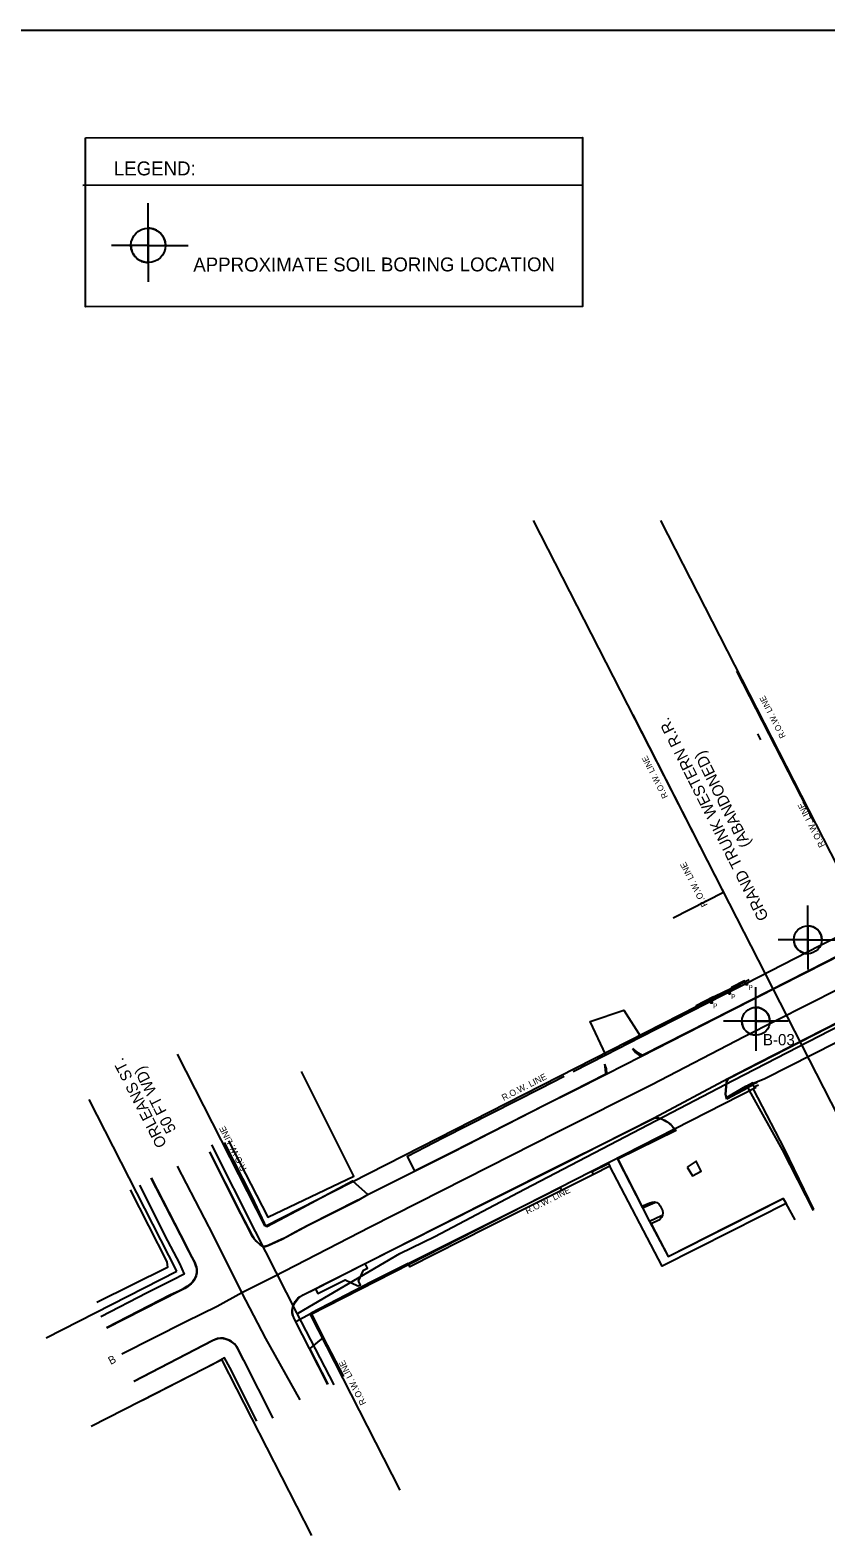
# Model space of a CAD drawing. Extents: x 19007.1 to 19038.2, y 21497.8 to 21516.9.
# Drawn here: x 19024.02 to 19030.01, y 21505.53 to 21516.88 of the extents above; entities that cross this region are included whole.
import ezdxf

# ---------------------------------------------------------------- set-up
doc = ezdxf.new("R2010")
doc.units = 0
for name, color, linetype in [('BORDER', 7, 'Continuous'), ('DETAIL_TEXT_DIMEN_PR', 7, 'Continuous'), ('G-ANNO-TTLB', 7, 'Continuous'), ('TYPICAL_TEXT_DIMEN_PR', 7, 'Continuous'), ('V-ANNO-TEXT', 7, 'Continuous'), ('V-BLDG-OTLN', 7, 'Continuous'), ('V-DEMO-PVMT', 7, 'Continuous'), ('V-PROP-RWAY', 7, 'Continuous'), ('V-PROP-RWAY-IDEN', 7, 'Continuous'), ('V-PVMT-CNTR', 7, 'Continuous'), ('V-PVMT-ROAD', 7, 'Continuous'), ('V-SITE-FEAT-DEMO', 7, 'Continuous'), ('V-SITE-FENC', 7, 'Continuous'), ('V-SITE-STRS', 7, 'Continuous'), ('V-SITE-WALK', 7, 'Continuous'), ('V-UTIL-OVHD', 7, 'Continuous')]:
    doc.layers.add(name, color=color, linetype=linetype)

msp = doc.modelspace()

# ---------------------------------------------------------------- linework, layer by layer
at = {"layer": 'G-ANNO-TTLB'}
msp.add_lwpolyline([(19036.423, 21497.766), (19007.08, 21497.766), (19007.08, 21516.881), (19036.423, 21516.881)], close=True, dxfattribs=at)
at = {"layer": 'TYPICAL_TEXT_DIMEN_PR'}
for p, q in [((19024.417, 21515.713), (19028.178, 21515.715)), ((19024.91, 21515.26), (19024.91, 21515.579)), ((19024.91, 21515.26), (19024.634, 21515.26)), ((19024.91, 21515.26), (19024.91, 21514.985)), ((19024.91, 21515.26), (19025.211, 21515.26)), ((19029.874, 21510.031), (19029.874, 21510.289)), ((19029.874, 21510.031), (19029.651, 21510.03)), ((19029.874, 21510.031), (19029.874, 21509.807)), ((19029.874, 21510.031), (19030.118, 21510.031)), ((19029.483, 21509.417), (19029.483, 21509.675)), ((19029.484, 21509.417), (19029.24, 21509.417)), ((19029.483, 21509.417), (19029.483, 21509.194)), ((19029.727, 21509.417), (19029.483, 21509.417))]:
    msp.add_line(p, q, dxfattribs=at)
msp.add_lwpolyline([(19024.437, 21516.071), (19028.178, 21516.073), (19028.179, 21514.8), (19024.438, 21514.797)], close=True, dxfattribs=at)
for points in [[(19024.91, 21515.39), (19024.91, 21515.26), (19025.04, 21515.26)], [(19024.91, 21515.13), (19024.91, 21515.26), (19024.78, 21515.26)], [(19029.874, 21510.136), (19029.874, 21510.031), (19029.979, 21510.031)], [(19029.874, 21509.925), (19029.874, 21510.031), (19029.769, 21510.031)], [(19029.483, 21509.522), (19029.483, 21509.417), (19029.588, 21509.417)], [(19029.483, 21509.312), (19029.483, 21509.417), (19029.378, 21509.417)]]:
    msp.add_lwpolyline(points, dxfattribs=at)
for centre, radius in [((19024.91, 21515.26), 0.13), ((19029.874, 21510.031), 0.105), ((19029.483, 21509.417), 0.105)]:
    msp.add_circle(centre, radius, dxfattribs=at)
for centre, radius, start, end in [((19024.91, 21515.26), 0.13, 0.0399, 90.0399), ((19024.91, 21515.26), 0.13, 180.0399, 270.0399), ((19029.874, 21510.031), 0.105, 0.0399, 90.0399), ((19029.874, 21510.031), 0.105, 180.0399, 270.0399), ((19029.483, 21509.417), 0.105, 0.0399, 90.0399), ((19029.483, 21509.417), 0.105, 180.0399, 270.0399)]:
    msp.add_arc(centre, radius, start, end, dxfattribs=at)
at = {"layer": 'V-BLDG-OTLN'}
for points in [[(19029.305, 21509.654), (19029.299, 21509.665), (19029.168, 21509.601), (19029.176, 21509.588)], [(19029.408, 21509.702), (19029.398, 21509.722), (19029.3, 21509.671), (19029.308, 21509.654)], [(19029.172, 21509.587), (19029.165, 21509.601), (19029.034, 21509.534), (19029.041, 21509.52)], [(19029.494, 21508.956), (19029.465, 21508.943), (19029.459, 21508.953), (19029.409, 21508.926), (19029.415, 21508.915), (19029.459, 21508.938), (19029.468, 21508.923), (19029.502, 21508.939)], [(19029.78, 21507.921), (19029.71, 21508.045), (19029.294, 21507.835), (19028.777, 21507.573), (19028.385, 21508.325), (19028.26, 21508.263), (19028.02, 21508.142), (19027.462, 21507.863), (19026.879, 21507.569), (19026.866, 21507.593), (19026.589, 21507.455), (19026.137, 21507.219), (19026.227, 21507.037), (19026.379, 21506.741)], [(19028.26, 21508.263), (19028.251, 21508.285), (19028.374, 21508.346), (19028.385, 21508.325)], [(19026.866, 21507.593), (19027.449, 21507.884), (19028.011, 21508.165), (19028.02, 21508.142)], [(19025.728, 21506.405), (19025.524, 21506.81), (19025.483, 21506.883), (19025.413, 21506.843), (19024.867, 21506.562)]]:
    msp.add_lwpolyline(points, dxfattribs=at)
at = {"layer": 'V-DEMO-PVMT'}
for points in [[(19028.097, 21508.889), (19028.362, 21509.022), (19028.49, 21509.087), (19028.616, 21509.152), (19029.3, 21509.501), (19030.016, 21509.866), (19030.652, 21510.19), (19030.704, 21510.219), (19030.996, 21510.373)], [(19028.108, 21509.039), (19028.353, 21509.164), (19028.617, 21509.301), (19029.241, 21509.619), (19029.408, 21509.702), (19029.965, 21509.988), (19030.523, 21510.268), (19030.468, 21510.372)], [(19028.555, 21509.213), (19028.585, 21509.187), (19028.628, 21509.161), (19029.299, 21509.504), (19030.015, 21509.868), (19030.59, 21510.166), (19030.626, 21510.182)], [(19028.305, 21508.482), (19028.718, 21508.689), (19029.272, 21508.987), (19029.505, 21509.106), (19030.229, 21509.475), (19030.738, 21509.734), (19030.887, 21509.807), (19031.202, 21509.968)], [(19029.262, 21508.846), (19029.258, 21508.867), (19029.265, 21508.958), (19029.277, 21508.987), (19029.507, 21509.104), (19030.228, 21509.473), (19030.74, 21509.732), (19030.888, 21509.804)], [(19028.554, 21509.212), (19028.578, 21509.182), (19028.616, 21509.152)], [(19028.097, 21508.891), (19028.354, 21509.021), (19028.351, 21509.057), (19028.347, 21509.093)], [(19028.362, 21509.022), (19028.358, 21509.058), (19028.347, 21509.093)], [(19029.265, 21508.831), (19029.255, 21508.868), (19029.262, 21508.957), (19029.272, 21508.987)], [(19028.306, 21508.481), (19028.718, 21508.687), (19028.724, 21508.689), (19028.738, 21508.691), (19028.751, 21508.689), (19028.778, 21508.679), (19028.812, 21508.66), (19028.828, 21508.649), (19028.852, 21508.627), (19028.863, 21508.615), (19028.869, 21508.608)], [(19028.718, 21508.689), (19028.746, 21508.688), (19028.759, 21508.686), (19028.778, 21508.681), (19028.796, 21508.673), (19028.808, 21508.666), (19028.83, 21508.651), (19028.842, 21508.64), (19028.865, 21508.616), (19028.882, 21508.594)], [(19028.869, 21508.608), (19028.879, 21508.594)]]:
    msp.add_lwpolyline(points, dxfattribs=at)
at = {"layer": 'V-PROP-RWAY'}
for p, q in [((19031.47, 21506.028), (19027.81, 21513.188)), ((19028.765, 21513.188), (19032.424, 21506.028)), ((19029.337, 21512.053), (19029.92, 21510.918)), ((19028.557, 21511.724), (19029.24, 21510.388)), ((19029.496, 21511.581), (19029.518, 21511.537)), ((19029.24, 21510.388), (19028.861, 21510.194)), ((19025.791, 21507.875), (19029.433, 21509.733)), ((19025.791, 21507.875), (19025.131, 21509.169)), ((19028.871, 21508.608), (19029.486, 21508.922)), ((19025.126, 21507.536), (19024.466, 21508.829)), ((19026.13, 21507.21), (19028.871, 21508.608)), ((19024.141, 21507.033), (19025.126, 21507.536)), ((19026.806, 21505.886), (19026.13, 21507.21)), ((19024.48, 21506.368), (19025.465, 21506.871)), ((19026.141, 21505.546), (19025.465, 21506.871))]:
    msp.add_line(p, q, dxfattribs=at)
at = {"layer": 'V-PVMT-CNTR'}
for points in [[(19024.711, 21506.912), (19025.192, 21507.157), (19025.429, 21507.272), (19025.614, 21507.374), (19025.854, 21507.494), (19026.581, 21507.868), (19027.297, 21508.234), (19027.984, 21508.583), (19028.701, 21508.941), (19029.396, 21509.302), (19030.11, 21509.663), (19030.749, 21509.989), (19031.403, 21510.322), (19032.101, 21510.681), (19032.774, 21511.026), (19033.516, 21511.404), (19034.256, 21511.778), (19034.944, 21512.128), (19035.373, 21512.345)], [(19026.053, 21506.566), (19025.794, 21507.028), (19025.615, 21507.374), (19025.401, 21507.805), (19025.131, 21508.327)]]:
    msp.add_lwpolyline(points, dxfattribs=at)
at = {"layer": 'V-PVMT-ROAD'}
for points in [[(19028.353, 21509.164), (19028.235, 21509.416), (19028.49, 21509.501), (19028.617, 21509.301)], [(19025.37, 21508.432), (19025.605, 21507.966), (19025.686, 21507.807), (19025.697, 21507.791), (19025.722, 21507.762), (19025.75, 21507.736), (19025.769, 21507.724), (19025.779, 21507.721), (19025.79, 21507.721), (19025.812, 21507.729), (19025.918, 21507.777), (19026.114, 21507.881), (19026.495, 21508.072), (19026.562, 21508.112), (19027.194, 21508.429), (19027.906, 21508.793), (19028.097, 21508.889)], [(19026.915, 21508.292), (19027.19, 21508.43), (19027.904, 21508.793), (19028.097, 21508.891)], [(19029.263, 21508.844), (19029.276, 21508.848), (19029.409, 21508.926)], [(19029.917, 21507.992), (19029.683, 21508.449), (19029.448, 21508.874), (19029.425, 21508.916), (19029.265, 21508.831)], [(19028.879, 21508.594), (19028.441, 21508.379), (19028.631, 21508.012), (19028.683, 21507.91), (19028.823, 21507.645), (19029.273, 21507.872), (19029.689, 21508.082), (19029.71, 21508.045)], [(19028.882, 21508.594), (19028.443, 21508.379), (19028.626, 21508.024), (19028.685, 21508.049), (19028.702, 21508.056), (19028.72, 21508.057), (19028.737, 21508.052), (19028.752, 21508.042), (19028.762, 21508.028), (19028.763, 21508.027), (19028.781, 21507.993), (19028.784, 21507.974), (19028.781, 21507.956), (19028.773, 21507.939), (19028.759, 21507.925), (19028.752, 21507.92), (19028.696, 21507.891), (19028.824, 21507.646), (19029.273, 21507.874), (19029.69, 21508.085)], [(19025.371, 21508.434), (19025.607, 21507.967), (19025.689, 21507.809), (19025.701, 21507.789), (19025.708, 21507.78), (19025.723, 21507.763), (19025.742, 21507.744), (19025.752, 21507.736), (19025.769, 21507.726), (19025.778, 21507.724), (19025.789, 21507.723), (19025.796, 21507.725), (19025.812, 21507.731), (19025.916, 21507.778), (19025.935, 21507.787), (19026.021, 21507.833), (19026.11, 21507.881), (19026.493, 21508.074)], [(19026.262, 21506.683), (19026.124, 21506.954), (19026.019, 21507.158), (19026.005, 21507.186), (19025.995, 21507.209), (19025.993, 21507.221), (19025.993, 21507.241), (19025.995, 21507.255), (19026.003, 21507.282), (19026.016, 21507.306), (19026.023, 21507.317), (19026.037, 21507.331), (19026.049, 21507.341), (19026.076, 21507.356), (19026.562, 21507.603), (19027.438, 21508.047), (19028.094, 21508.376), (19028.305, 21508.482)], [(19026.02, 21507.157), (19026.006, 21507.186), (19026.001, 21507.198), (19025.996, 21507.222), (19025.996, 21507.242), (19025.998, 21507.256), (19026.006, 21507.282), (19026.015, 21507.299), (19026.022, 21507.31), (19026.039, 21507.329), (19026.062, 21507.348), (19026.076, 21507.356), (19026.168, 21507.402), (19026.543, 21507.592), (19027.439, 21508.045), (19028.095, 21508.375), (19028.306, 21508.481)], [(19028.965, 21508.318), (19029.007, 21508.254), (19029.072, 21508.289), (19029.033, 21508.364), (19028.965, 21508.318)], [(19024.93, 21508.235), (19025.151, 21507.809), (19025.212, 21507.685), (19025.237, 21507.639), (19025.257, 21507.598), (19025.266, 21507.576), (19025.27, 21507.564), (19025.273, 21507.548), (19025.273, 21507.523), (19025.268, 21507.499), (19025.264, 21507.489), (19025.253, 21507.469), (19025.243, 21507.455), (19025.23, 21507.442), (19025.201, 21507.42), (19025.164, 21507.397), (19025.144, 21507.387), (19025.078, 21507.356), (19024.596, 21507.108)], [(19024.933, 21508.237), (19025.152, 21507.809), (19025.239, 21507.641), (19025.26, 21507.6), (19025.269, 21507.577), (19025.273, 21507.566), (19025.275, 21507.549), (19025.275, 21507.524), (19025.27, 21507.499), (19025.263, 21507.483), (19025.252, 21507.462), (19025.245, 21507.453), (19025.233, 21507.44), (19025.224, 21507.432), (19025.205, 21507.418), (19025.185, 21507.406), (19025.144, 21507.386), (19024.598, 21507.106)], [(19024.775, 21508.149), (19025.049, 21507.605), (19025.055, 21507.564), (19024.522, 21507.3)], [(19026.171, 21507.394), (19026.186, 21507.367), (19026.391, 21507.469), (19026.488, 21507.425), (19026.507, 21507.433), (19026.493, 21507.461), (19026.53, 21507.544), (19026.56, 21507.559), (19026.543, 21507.592)], [(19026.02, 21507.157), (19026.137, 21507.219)], [(19026.227, 21507.037), (19026.125, 21506.954)], [(19025.849, 21506.429), (19025.63, 21506.866), (19025.583, 21506.954), (19025.576, 21506.966), (19025.558, 21506.988), (19025.533, 21507.008), (19025.519, 21507.016), (19025.49, 21507.027), (19025.475, 21507.031), (19025.453, 21507.032), (19025.432, 21507.029), (19025.419, 21507.024), (19025.392, 21507.012), (19024.802, 21506.705)], [(19025.628, 21506.865), (19025.581, 21506.955), (19025.574, 21506.967), (19025.557, 21506.987), (19025.545, 21506.997), (19025.519, 21507.013), (19025.49, 21507.024), (19025.475, 21507.027), (19025.453, 21507.029), (19025.433, 21507.026), (19025.419, 21507.022), (19025.393, 21507.011), (19024.803, 21506.704)], [(19026.264, 21506.684), (19026.125, 21506.954)]]:
    msp.add_lwpolyline(points, dxfattribs=at)
at = {"layer": 'V-SITE-FEAT-DEMO'}
for centre, radius in [((19029.414, 21509.697), 0.00597), ((19029.414, 21509.697), 0.00299), ((19029.149, 21509.559), 0.00597), ((19029.149, 21509.559), 0.00299), ((19029.285, 21509.628), 0.00597), ((19029.285, 21509.628), 0.00299)]:
    msp.add_circle(centre, radius, dxfattribs=at)
at = {"layer": 'V-SITE-FENC'}
for points in [[(19025.515, 21508.516), (19025.811, 21507.943), (19026.456, 21508.251), (19026.064, 21509.039)], [(19029.919, 21508), (19029.699, 21508.457), (19029.464, 21508.907)]]:
    msp.add_lwpolyline(points, dxfattribs=at)
at = {"layer": 'V-SITE-STRS'}
for points in [[(19028.631, 21508.012), (19028.723, 21508.052)], [(19028.773, 21507.952), (19028.683, 21507.91)]]:
    msp.add_lwpolyline(points, dxfattribs=at)
at = {"layer": 'V-SITE-WALK'}
for points in [[(19029.263, 21508.844), (19029.408, 21508.928), (19029.551, 21508.987), (19030.268, 21509.35), (19030.603, 21509.523), (19030.614, 21509.505)], [(19026.915, 21508.293), (19026.861, 21508.401), (19027.132, 21508.541), (19027.859, 21508.911), (19028.039, 21509.003)], [(19025.481, 21508.505), (19025.69, 21508.096), (19025.783, 21507.896), (19025.803, 21507.871), (19025.94, 21507.944), (19026.073, 21508.014), (19026.268, 21508.12), (19026.447, 21508.216), (19026.562, 21508.112)], [(19024.843, 21508.183), (19025.056, 21507.764), (19025.144, 21507.592), (19025.181, 21507.513), (19025.093, 21507.468), (19024.903, 21507.373), (19024.553, 21507.191)]]:
    msp.add_lwpolyline(points, dxfattribs=at)
at = {"layer": 'V-UTIL-OVHD'}
for points in [[(19026.038, 21507.219), (19026.804, 21507.669), (19027.068, 21507.797), (19027.741, 21508.152), (19029.314, 21508.974), (19031.251, 21509.972), (19031.886, 21510.285), (19032.984, 21510.845)], [(19025.385, 21508.487), (19025.714, 21507.833), (19026.025, 21507.222), (19026.307, 21506.68)]]:
    msp.add_lwpolyline(points, dxfattribs=at)

# ---------------------------------------------------------------- texts
msp.add_text('B', height=0.0597, rotation=27.0313).set_placement((19024.627, 21506.829))
at = {"layer": 'BORDER'}
for s, height, p in [('LEGEND:', 0.105, (19024.651, 21515.787)), ('APPROXIMATE SOIL BORING LOCATION', 0.10498, (19025.249, 21515.063))]:
    msp.add_text(s, height=height, rotation=0.0399, dxfattribs=at).set_placement(p)
at = {"layer": 'DETAIL_TEXT_DIMEN_PR'}
msp.add_text('B-03', height=0.085, rotation=0.0399, dxfattribs=at).set_placement((19029.536, 21509.236))
at = {"layer": 'V-ANNO-TEXT'}
for s, height, rotation, p in [('GRAND TRUNK WESTERN R.R.', 0.08503, 116.6596, (19029.582, 21510.2)), ('(ABANDONED)', 0.08503, 116.6596, (19029.448, 21510.751)), ('ORLEANS ST. ', 0.08361, 117.0313, (19025.052, 21508.491)), ('50 FT WD)', 0.0836, 117.0313, (19025.122, 21508.6))]:
    msp.add_text(s, height=height, rotation=rotation, dxfattribs=at).set_placement(p)
at = {"layer": 'V-PROP-RWAY-IDEN'}
for height, rotation, p in [(0.04535, 117.1686, (19029.709, 21511.562)), (0.04535, 117.1686, (19028.823, 21511.109)), (0.04778, 117.0313, (19030.005, 21510.741)), (0.04778, 117.0313, (19029.121, 21510.293)), (0.04778, 27.0313, (19027.585, 21508.817)), (0.04778, 117.0313, (19025.652, 21508.305)), (0.04778, 27.0313, (19027.763, 21507.963)), (0.04778, 117.0313, (19026.552, 21506.541))]:
    msp.add_text('R.O.W. LINE', height=height, rotation=rotation, dxfattribs=at).set_placement(p)
at = {"layer": 'V-SITE-FEAT-DEMO'}
for p in [(19029.427, 21509.653), (19029.161, 21509.515), (19029.297, 21509.584)]:
    msp.add_text('P', height=0.0358, rotation=360, dxfattribs=at).set_placement(p)

doc.saveas('drawing.dxf')
